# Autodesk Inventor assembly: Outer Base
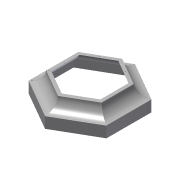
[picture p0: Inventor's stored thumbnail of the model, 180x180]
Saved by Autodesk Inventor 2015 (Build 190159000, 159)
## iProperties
Created: 2013-06
Part Number: Outer Base
Document SubType Name: Assembly
Designer: 1103005
Author: 1103005
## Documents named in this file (2)
- C:\Users\rsheridan\Desktop\Dave's Inventor\Sau Paulo Chimnea\Outer Base.iam
- C:\Users\rsheridan\Desktop\Dave's Inventor\Sau Paulo Chimnea\Outer Base Flange.ipt
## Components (6 placed, 1 different names)
1. Outer Base Flange:1
2. Outer Base Flange:2
3. Outer Base Flange:3
4. Outer Base Flange:4
5. Outer Base Flange:5
6. Outer Base Flange:6
